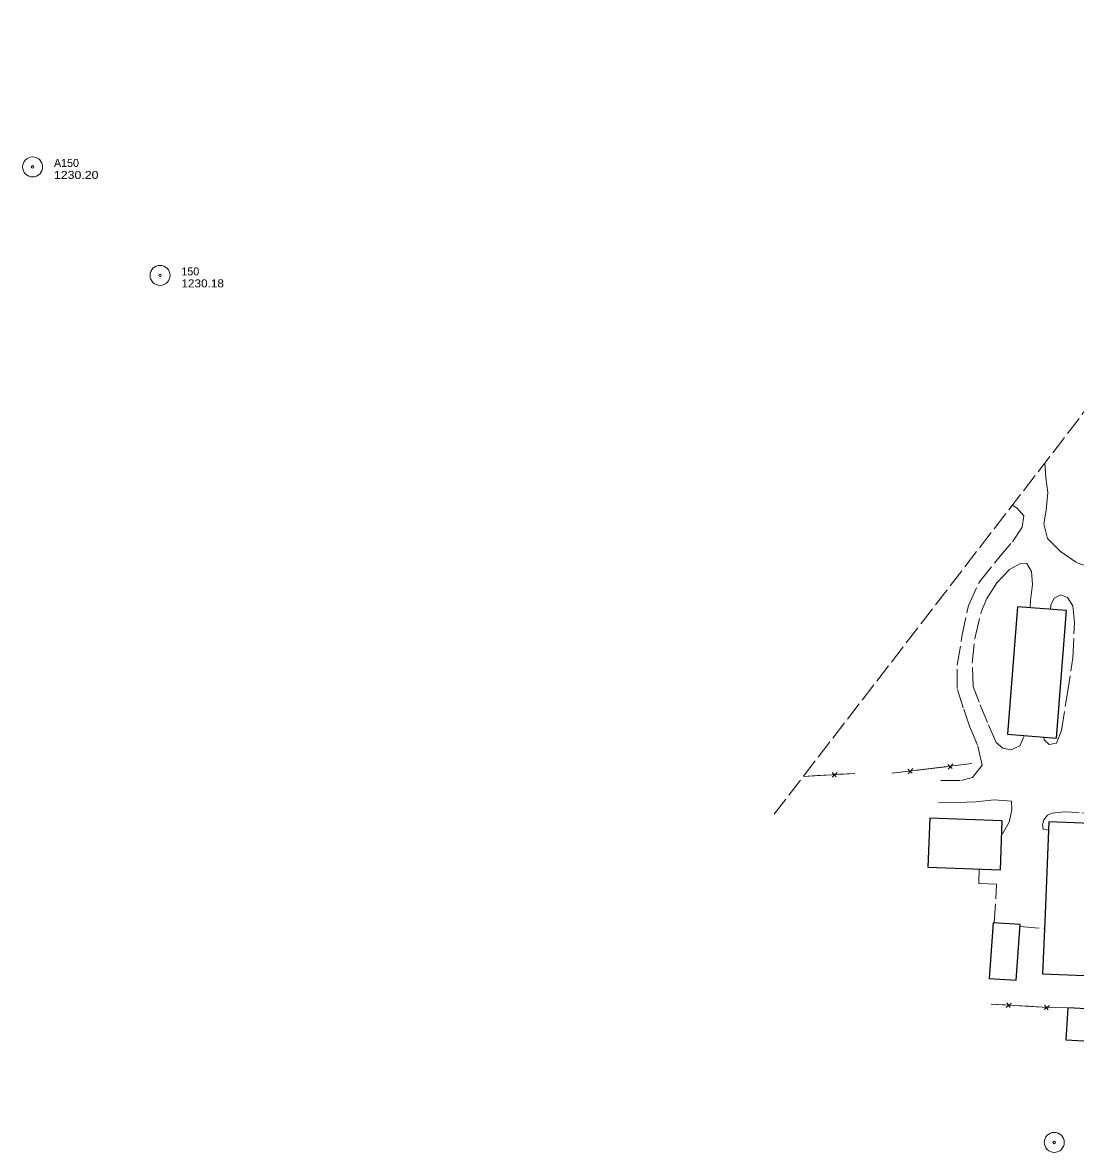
# Model space of a CAD drawing. Extents: x 299311 to 301657, y 49513 to 51866.
# Drawn here: x 299311 to 300100, y 50222 to 51068 of the extents above; entities that cross this region are included whole.
import ezdxf

# ---------------------------------------------------------------- set-up
doc = ezdxf.new("R2010")
doc.units = 0
doc.header["$LTSCALE"] = 2.4
doc.linetypes.add('LONG_DASHED', pattern=[7.5, 6, -1.5])
for name, color, linetype, lineweight in [('12', 7, 'Continuous', 25), ('15', 7, 'Continuous', 13), ('17', 7, 'LONG_DASHED', 13), ('4', 7, 'Continuous', 13), ('6', 7, 'Continuous', 13)]:
    doc.layers.add(name, color=color, linetype=linetype, lineweight=lineweight)

msp = doc.modelspace()

# ---------------------------------------------------------------- linework, layer by layer
at = {"layer": '12'}
for points in [[(300085.692, 50532.263), (300093.112, 50627.752), (300056.399, 50630.605), (300048.979, 50535.116)], [(299989.257, 50435.404), (300043.691, 50433.42), (300045.028, 50470.099), (299990.594, 50472.083)], [(300075.204, 50355.583), (300150.684, 50352.453), (300152.523, 50396.811), (300143.36, 50397.191), (300143.912, 50410.516), (300134.414, 50410.91), (300135.256, 50431.215), (300151.36, 50430.548), (300151.947, 50444.691), (300136.039, 50445.35), (300136.945, 50467.2), (300079.901, 50469.565), (300077.032, 50400.381), (300077.062, 50400.38)], [(300055.407, 50350.657), (300058.304, 50392.395), (300038.171, 50393.792), (300035.274, 50352.054)], [(300092.717, 50305.97), (300180.635, 50301.154), (300181.955, 50325.26), (300094.037, 50330.076)]]:
    msp.add_lwpolyline(points, close=True, dxfattribs=at)
at = {"layer": '15'}
for p, q in [((299917.594, 50506.313), (299920.638, 50503.24)), ((299917.613, 50502.995), (299921.216, 50506.524)), ((299962.21, 50505.864), (300022.11, 50513.041)), ((299962.21, 50505.864), (299972.914, 50507.147)), ((299974.151, 50508.93), (299977.565, 50505.882)), ((299974.385, 50505.426), (299977.964, 50509.387)), ((299979.99, 50507.994), (299992.16, 50509.452)), ((299992.16, 50509.452), (300002.864, 50510.735)), ((300004.101, 50512.519), (300007.515, 50509.47)), ((300004.335, 50509.015), (300007.914, 50512.976)), ((300009.94, 50511.583), (300022.11, 50513.041)), ((299896.003, 50503.519), (299934.609, 50505.766)), ((299896.003, 50503.519), (299906.156, 50504.11)), ((299906.156, 50504.11), (299916.325, 50504.702)), ((299923.047, 50505.093), (299934.609, 50505.766)), ((300036.779, 50332.847), (300046.905, 50332.259)), ((300047.982, 50330.422), (300051.954, 50333.497)), ((300048.347, 50333.706), (300051.003, 50330.316)), ((300053.599, 50331.87), (300065.113, 50331.202)), ((300065.113, 50331.202), (300075.239, 50330.614)), ((300076.316, 50328.777), (300080.288, 50331.852)), ((300076.68, 50332.061), (300079.337, 50328.671)), ((300081.937, 50330.314), (300093.466, 50330.012))]:
    msp.add_line(p, q, dxfattribs=at)
msp.add_lwpolyline([(300036.779, 50332.847), (300079.132, 50330.388), (300093.466, 50330.012)], dxfattribs=at)
at = {"layer": '17'}
msp.add_line((300058.207, 50391.003), (300076.613, 50389.543), dxfattribs=at)
for points in [[(300076.821, 50738.367), (300077.729, 50727.23), (300079.083, 50716.341), (300077.863, 50702.938), (300076.239, 50692.819), (300078.836, 50681.762), (300088.734, 50671.932), (300101.113, 50663.594), (300114.673, 50658.749), (300141.588, 50649.285), (300171.277, 50646.24), (300192.937, 50644.404), (300217.288, 50643.397), (300236.283, 50641.204), (300253.254, 50637.828), (300300.251, 50624.664), (300341.768, 50617.194), (300363.145, 50615.021), (300373.097, 50615.103), (300377.484, 50617.292), (300380.635, 50619.728), (300383.879, 50623.635)], [(299998.858, 50500.462), (300014.021, 50500.315), (300022.706, 50502.729), (300030.001, 50512.029), (300026.467, 50526.78), (300020.802, 50540.366), (300015.721, 50554.988), (300011.123, 50569.426), (300011.293, 50586.904), (300014.787, 50608.381), (300019.619, 50631.658), (300027.852, 50649.212), (300042.042, 50667.04), (300052.744, 50679.354), (300059.842, 50690.334), (300061.147, 50698.705), (300056.173, 50704.481), (300052.456, 50706.722)], [(300061.535, 50534.14), (300060.817, 50532.594), (300058.158, 50526.489), (300051.767, 50523.517), (300045.501, 50524.581), (300040.506, 50528.925), (300034.013, 50543.791), (300027.626, 50559.19), (300023.124, 50570.829), (300022.496, 50588.461), (300024.6, 50607.843), (300029.374, 50627.299), (300033.351, 50636.894), (300040.97, 50648.642), (300050.365, 50658.636), (300058.25, 50662.851), (300063.313, 50663.004), (300066.906, 50657.154), (300067.733, 50647.29), (300066.192, 50635.373), (300065.799, 50629.874)], [(300076.164, 50533.003), (300076.369, 50530.977), (300080.032, 50527.411), (300085.628, 50528.465), (300089.415, 50538.005), (300093.627, 50564.522), (300097.849, 50592.346), (300099.102, 50618.832), (300097.745, 50631.206), (300093.868, 50637.631), (300088.944, 50639.486), (300083.952, 50637.074), (300081.393, 50631.931), (300081.018, 50628.692)], [(300044.671, 50460.314), (300045.245, 50460.548), (300050.201, 50469.239), (300052.242, 50478.456), (300051.823, 50484.892), (300038.828, 50485.984), (300025.277, 50484.519), (300010.9, 50483.831), (299997.256, 50483.742)], [(300135.136, 50428.313), (300145.034, 50426.682), (300150.079, 50426.555), (300154.774, 50429.152), (300159.582, 50444.074), (300159.043, 50453.242), (300152.867, 50462.22), (300143.726, 50467.655), (300134.75, 50471.645), (300119.03, 50475.313), (300102.604, 50476.359), (300091.393, 50476.983), (300082.47, 50476.033), (300078.91, 50474.449), (300076.048, 50470.85), (300075.066, 50467.222), (300075.651, 50464.031), (300078.495, 50463.4), (300079.637, 50463.196)], [(300038.913, 50393.741), (300040.773, 50422.617), (300027.321, 50423.227), (300027.568, 50434.008)]]:
    msp.add_lwpolyline(points, dxfattribs=at)
at = {"layer": '4', "linetype": 'LONG_DASHED'}
msp.add_line((300552.76, 51356.525), (299872.076, 50472.442), dxfattribs=at)
at = {"layer": '6'}
for centre, radius in [((299318.349, 50960.239), 7.5), ((299318.349, 50960.239), 0.96), ((299413.842, 50878.97), 7.5), ((299413.842, 50878.97), 0.96), ((300083.958, 50229.202), 7.5), ((300083.958, 50229.202), 0.96)]:
    msp.add_circle(centre, radius, dxfattribs=at)

# ---------------------------------------------------------------- texts
for s, p in [('A150', (299334.349, 50960.239)), ('150', (299429.842, 50878.97))]:
    msp.add_text(s, height=6, dxfattribs=at).set_placement(p)
for s, width, p in [('1230.20', 1.15, (299334.349, 50951.239)), ('1230.18', 1.1, (299429.842, 50869.97))]:
    msp.add_text(s, height=6, dxfattribs=dict(at, width=width)).set_placement(p)

doc.saveas('drawing.dxf')
